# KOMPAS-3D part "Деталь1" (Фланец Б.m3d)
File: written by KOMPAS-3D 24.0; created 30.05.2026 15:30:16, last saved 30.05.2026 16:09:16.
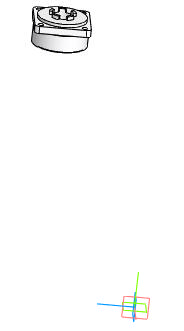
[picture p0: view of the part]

Document properties: Автор: R2D2; Полное имя файла: E:\Работа\Зайцев\GVWR2434M-2W-F-ОСТ Задвижка клиновая с выдвижным штоком DN.ru Ду50-300 Ру25\исходные материалы\DN250\Фланец Б.m3d

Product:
- Body: Твердое тело1  | qty 1
    Масса: 5.664552
- Part/product: Деталь1
    Масса: 5.664552
    additional columns: Типовые

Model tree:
1. Твердое тело1  (labels: Твердое тело1)
2. Эскиз:1  (labels: Грань.Твердое тело1)
3. Элемент вращения:1
     Угол 1 = 360
4. Эскиз:2  (labels: Грань.Твердое тело1; Ребро.Твердое тело1)
5. Эскиз:3  (labels: Грань.Твердое тело1; Ребро.Твердое тело1)
6. Элемент выдавливания:1
     Расстояние 1 = 10
7. Элемент выдавливания:2  (labels: Грань.Твердое тело1)
     Расстояние 2 = 7
8. Эскиз:4  (labels: Грань.Твердое тело1; Ребро.Твердое тело1)
9. Элемент выдавливания:3  (labels: Грань.Твердое тело1)
     Расстояние 1 = 16
10. Эскиз:5  (labels: Грань.Твердое тело1; Ребро.Твердое тело1)
11. Элемент выдавливания:4
     Расстояние 1 = 7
